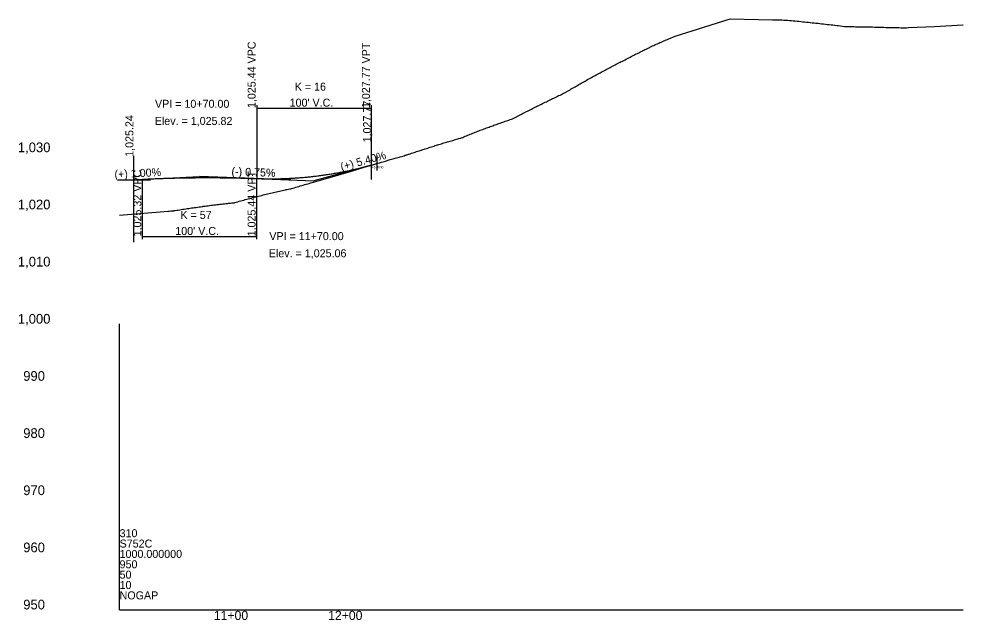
# Model space of a CAD drawing. Extents: x 1590191 to 1593577, y 1108634 to 1115609.
# Drawn here: x 1590191 to 1591017, y 1110634 to 1111160 of the extents above; entities that cross this region are included whole.
import ezdxf

# ---------------------------------------------------------------- set-up
doc = ezdxf.new("R2010")
doc.units = 0
for name, color, linetype in [('BR_USER NOTES', 7, 'Continuous'), ('RD_DDB_ElevTX', 7, 'Continuous'), ('RD_DDB_GradeTX', 7, 'Continuous'), ('RD_DDB_Profile_EX', 7, 'Continuous'), ('RD_DDB_Profile_Lbl', 7, 'Continuous'), ('RD_DDB_Profile_PR', 7, 'Continuous'), ('RD_DDB_StaTX', 7, 'Continuous'), ('RD_DDB_StripGrade', 7, 'Continuous'), ('RD_DDB_VCLbl', 7, 'Continuous'), ('RD_GPK_Profile_Cell', 7, 'Continuous')]:
    doc.layers.add(name, color=color, linetype=linetype)

msp = doc.modelspace()

# ---------------------------------------------------------------- linework, layer by layer
at = {"layer": 'BR_USER NOTES'}
for p, q in [((1590499.01, 1111048.43), (1590499.01, 1111019.91)), ((1590291.08, 1111040.52), (1590291.08, 1110965.03)), ((1590499.01, 1111032.31), (1590504.01, 1111033.78)), ((1590504.01, 1111040.83), (1590504.01, 1111027.61)), ((1590277.69, 1111019.67), (1590305.95, 1111019.67))]:
    msp.add_line(p, q, dxfattribs=at)
at = {"layer": 'RD_DDB_GradeTX'}
for p, q in [((1590499.01, 1111032.31), (1590449.01, 1111018.8)), ((1590291.08, 1111019.67), (1590349.01, 1111022.57)), ((1590428.95, 1111019.55), (1590349.01, 1111022.57)), ((1590369.07, 1111021.81), (1590449.01, 1111018.8))]:
    msp.add_line(p, q, dxfattribs=at)
at = {"layer": 'RD_DDB_Profile_EX'}
msp.add_lwpolyline([(1590279.01, 1110988.58), (1590289.38, 1110989.65), (1590314.38, 1110991.63), (1590321.21, 1110992.17), (1590322.52, 1110992.27), (1590323.82, 1110992.37), (1590325.12, 1110992.47), (1590326.42, 1110992.57), (1590326.86, 1110992.6), (1590327.76, 1110992.75), (1590329.02, 1110992.94), (1590330.33, 1110993.15), (1590331.63, 1110993.35), (1590332.93, 1110993.55), (1590334.23, 1110993.74), (1590335.53, 1110993.94), (1590336.84, 1110994.14), (1590338.14, 1110994.33), (1590339.44, 1110994.52), (1590340.74, 1110994.72), (1590342.04, 1110994.91), (1590343.34, 1110995.1), (1590344.65, 1110995.29), (1590345.95, 1110995.47), (1590347.25, 1110995.66), (1590348.55, 1110995.84), (1590349.85, 1110996.03), (1590351.16, 1110996.21), (1590351.84, 1110996.31), (1590352.46, 1110996.39), (1590353.01, 1110996.46), (1590353.76, 1110996.57), (1590355.06, 1110996.75), (1590356.36, 1110996.92), (1590357.67, 1110997.1), (1590358.97, 1110997.28), (1590360.27, 1110997.45), (1590361.57, 1110997.63), (1590362.39, 1110997.73), (1590362.87, 1110997.79), (1590364.17, 1110997.95), (1590365.48, 1110998.1), (1590366.78, 1110998.25), (1590368.08, 1110998.4), (1590369.38, 1110998.54), (1590370.68, 1110998.69), (1590371.99, 1110998.83), (1590373.29, 1110998.97), (1590374.22, 1110999.07), (1590374.59, 1110999.09), (1590375.89, 1110999.18), (1590377.19, 1110999.28), (1590378.49, 1110999.39), (1590379.26, 1110999.46), (1590379.8, 1110999.62), (1590381.1, 1111000), (1590382.4, 1111000.38), (1590383.7, 1111000.75), (1590385, 1111001.12), (1590386.31, 1111001.49), (1590387.61, 1111001.85), (1590388.91, 1111002.22), (1590390.21, 1111002.57), (1590391.51, 1111002.93), (1590392.81, 1111003.28), (1590394.12, 1111003.63), (1590395.42, 1111003.98), (1590396.72, 1111004.33), (1590398.02, 1111004.67), (1590398.38, 1111004.76), (1590399.32, 1111004.99), (1590400.63, 1111005.31), (1590401.93, 1111005.63), (1590403.23, 1111005.95), (1590403.99, 1111006.13), (1590404.62, 1111006.28), (1590405.83, 1111006.57), (1590407.13, 1111006.89), (1590408.44, 1111007.2), (1590409.74, 1111007.51), (1590411.04, 1111007.82), (1590412.34, 1111008.13), (1590413.64, 1111008.43), (1590414.95, 1111008.74), (1590416.25, 1111009.04), (1590417.55, 1111009.34), (1590418.85, 1111009.64), (1590420.15, 1111009.94), (1590421.45, 1111010.24), (1590422.76, 1111010.54), (1590424.06, 1111010.83), (1590424.64, 1111010.97), (1590425.36, 1111011.12), (1590426.66, 1111011.4), (1590427.96, 1111011.67), (1590428.48, 1111011.78), (1590429.27, 1111011.97), (1590430.57, 1111012.25), (1590431.87, 1111012.52), (1590433.17, 1111013), (1590434.47, 1111013.39), (1590435.77, 1111013.78), (1590437.08, 1111014.17), (1590438.38, 1111014.55), (1590439.68, 1111014.94), (1590440.98, 1111015.32), (1590442.28, 1111015.7), (1590443.59, 1111016.09), (1590444.89, 1111016.47), (1590446.19, 1111016.85), (1590447.49, 1111017.22), (1590447.49, 1111017.22), (1590456.83, 1111019.94), (1590481.79, 1111027.18), (1590481.83, 1111027.2), (1590492.91, 1111030.49), (1590494, 1111030.82), (1590495.1, 1111031.14), (1590496.19, 1111031.47), (1590497.28, 1111031.79), (1590498.37, 1111032.12), (1590499.46, 1111032.44), (1590500.56, 1111032.76), (1590501.65, 1111033.09), (1590502.74, 1111033.41), (1590503.83, 1111033.73), (1590504.92, 1111034.05), (1590506.02, 1111034.37), (1590506.65, 1111034.56), (1590507.11, 1111034.69), (1590508.2, 1111035.02), (1590509.29, 1111035.34), (1590510.38, 1111035.66), (1590511.56, 1111036.01), (1590512.57, 1111036.3), (1590513.66, 1111036.62), (1590514.75, 1111036.94), (1590515.84, 1111037.25), (1590516.94, 1111037.57), (1590518.03, 1111037.88), (1590519.12, 1111038.2), (1590520.21, 1111038.51), (1590521.3, 1111038.82), (1590522.4, 1111039.13), (1590523.49, 1111039.44), (1590524.58, 1111039.75), (1590525.67, 1111040.06), (1590526.76, 1111040.37), (1590527.86, 1111040.67), (1590528.95, 1111040.98), (1590529.64, 1111041.17), (1590530.04, 1111041.3), (1590531.13, 1111041.66), (1590531.75, 1111041.87), (1590532.23, 1111042.03), (1590533.32, 1111042.39), (1590534.41, 1111042.75), (1590535.5, 1111043.12), (1590536.59, 1111043.48), (1590537.69, 1111043.84), (1590538.78, 1111044.2), (1590539.87, 1111044.56), (1590540.96, 1111044.91), (1590542.05, 1111045.27), (1590543.15, 1111045.63), (1590544.24, 1111045.98), (1590545.33, 1111046.34), (1590546.42, 1111046.69), (1590547.51, 1111047.04), (1590548.61, 1111047.39), (1590549.7, 1111047.74), (1590550.79, 1111048.09), (1590551.88, 1111048.43), (1590552.97, 1111048.78), (1590554.07, 1111049.12), (1590554.56, 1111049.28), (1590555.16, 1111049.46), (1590556.25, 1111049.8), (1590557.03, 1111050.04), (1590557.34, 1111050.13), (1590558.43, 1111050.47), (1590559.53, 1111050.81), (1590560.62, 1111051.15), (1590561.71, 1111051.49), (1590562.8, 1111051.83), (1590563.9, 1111052.16), (1590564.99, 1111052.5), (1590565.97, 1111052.8), (1590567.17, 1111053.14), (1590568.26, 1111053.46), (1590569.36, 1111053.77), (1590570.45, 1111054.08), (1590571.54, 1111054.39), (1590572.63, 1111054.69), (1590573.72, 1111054.99), (1590574.84, 1111055.3), (1590575.91, 1111055.6), (1590577, 1111055.89), (1590577.63, 1111056.06), (1590578.09, 1111056.26), (1590579.18, 1111056.72), (1590580.28, 1111057.17), (1590581.37, 1111057.62), (1590582.46, 1111058.07), (1590583.55, 1111058.52), (1590584.64, 1111058.97), (1590585.74, 1111059.41), (1590586.83, 1111059.85), (1590587.92, 1111060.29), (1590589.01, 1111060.72), (1590590.1, 1111061.16), (1590591.2, 1111061.59), (1590592.29, 1111062.01), (1590593.38, 1111062.44), (1590594.47, 1111062.86), (1590595.57, 1111063.28), (1590596.66, 1111063.7), (1590597.83, 1111064.14), (1590598.84, 1111064.51), (1590599.93, 1111064.92), (1590601.03, 1111065.32), (1590602.24, 1111065.76), (1590603.21, 1111066.11), (1590604.3, 1111066.51), (1590605.39, 1111066.91), (1590606.49, 1111067.31), (1590607.24, 1111067.58), (1590607.58, 1111067.7), (1590608.67, 1111068.09), (1590609.76, 1111068.48), (1590610.85, 1111068.87), (1590611.95, 1111069.25), (1590613.04, 1111069.63), (1590614.13, 1111070.01), (1590615.22, 1111070.39), (1590616.31, 1111070.76), (1590617.41, 1111071.13), (1590618.5, 1111071.5), (1590619.59, 1111071.87), (1590620.68, 1111072.24), (1590621.77, 1111072.6), (1590622.87, 1111072.96), (1590623.96, 1111073.36), (1590625.05, 1111073.97), (1590626.14, 1111074.57), (1590626.47, 1111074.75), (1590627.23, 1111075.16), (1590628.33, 1111075.74), (1590629.42, 1111076.33), (1590630.51, 1111076.91), (1590631.6, 1111077.49), (1590632.7, 1111078.06), (1590633.4, 1111078.44), (1590633.79, 1111078.63), (1590634.88, 1111079.19), (1590635.97, 1111079.75), (1590637.06, 1111080.3), (1590638.16, 1111080.86), (1590639.25, 1111081.41), (1590640.34, 1111081.96), (1590641.43, 1111082.51), (1590642.52, 1111083.06), (1590643.62, 1111083.61), (1590644.71, 1111084.16), (1590645.8, 1111084.71), (1590646.89, 1111085.25), (1590647.3, 1111085.46), (1590647.98, 1111085.79), (1590649.08, 1111086.33), (1590649.48, 1111086.53), (1590650.17, 1111086.84), (1590650.76, 1111087.12), (1590651.26, 1111087.36), (1590652.35, 1111087.9), (1590653.44, 1111088.44), (1590654.54, 1111088.98), (1590655.63, 1111089.51), (1590656.72, 1111090.05), (1590657.81, 1111090.58), (1590658.9, 1111091.12), (1590660, 1111091.65), (1590661.09, 1111092.18), (1590662.18, 1111092.71), (1590663.27, 1111093.23), (1590664.37, 1111093.76), (1590665.46, 1111094.29), (1590666.55, 1111094.81), (1590667.64, 1111095.33), (1590668.76, 1111095.87), (1590669.83, 1111096.47), (1590670.31, 1111096.74), (1590670.92, 1111097.1), (1590672.01, 1111097.74), (1590673.1, 1111098.39), (1590674.19, 1111099.03), (1590675.29, 1111099.67), (1590676.38, 1111100.3), (1590677.47, 1111100.94), (1590678.56, 1111101.57), (1590679.65, 1111102.2), (1590680.75, 1111102.84), (1590681.84, 1111103.46), (1590682.93, 1111104.09), (1590684.02, 1111104.72), (1590685.11, 1111105.34), (1590686.21, 1111105.96), (1590687.3, 1111106.58), (1590688.39, 1111107.2), (1590689.48, 1111107.81), (1590690.57, 1111108.43), (1590691.87, 1111109.15), (1590692.76, 1111109.64), (1590693.85, 1111110.23), (1590694.94, 1111110.82), (1590696.03, 1111111.41), (1590697.13, 1111112), (1590698.22, 1111112.59), (1590699.31, 1111113.17), (1590700.4, 1111113.77), (1590701.5, 1111114.36), (1590702.59, 1111114.95), (1590703.68, 1111115.54), (1590704.77, 1111116.12), (1590705.86, 1111116.7), (1590706.96, 1111117.29), (1590708.05, 1111117.86), (1590709.14, 1111118.44), (1590710.23, 1111119.01), (1590711.32, 1111119.58), (1590712.42, 1111120.15), (1590713.51, 1111120.72), (1590714.6, 1111121.28), (1590715.08, 1111121.53), (1590715.69, 1111121.84), (1590716.78, 1111122.38), (1590717.92, 1111122.93), (1590718.97, 1111123.48), (1590720.06, 1111124.06), (1590721.15, 1111124.63), (1590722.24, 1111125.2), (1590723.34, 1111125.76), (1590724.43, 1111126.33), (1590725.52, 1111126.89), (1590726.61, 1111127.45), (1590727.7, 1111128), (1590728.8, 1111128.56), (1590729.89, 1111129.11), (1590730.98, 1111129.66), (1590732.07, 1111130.2), (1590733.17, 1111130.74), (1590734.26, 1111131.28), (1590735.35, 1111131.82), (1590736.07, 1111132.17), (1590736.44, 1111132.36), (1590737.53, 1111132.91), (1590738.63, 1111133.46), (1590739.72, 1111134), (1590740.81, 1111134.54), (1590741.9, 1111135.07), (1590742.99, 1111135.6), (1590744.09, 1111136.13), (1590745.18, 1111136.64), (1590746.27, 1111137.14), (1590747.36, 1111137.64), (1590748.45, 1111138.14), (1590749.55, 1111138.63), (1590750.64, 1111139.12), (1590751.73, 1111139.61), (1590752.82, 1111140.09), (1590753.91, 1111140.57), (1590755.01, 1111141.05), (1590756.1, 1111141.52), (1590757.19, 1111141.99), (1590758.28, 1111142.45), (1590759.37, 1111142.91), (1590765.13, 1111145.32), (1590790.07, 1111153.14), (1590813.06, 1111160.35), (1590838.05, 1111159.85), (1590850.2, 1111159.6), (1590851.85, 1111159.56), (1590853.54, 1111159.53), (1590855.16, 1111159.49), (1590856.81, 1111159.45), (1590858.46, 1111159.4), (1590860.11, 1111159.36), (1590861.76, 1111159.31), (1590863.04, 1111159.25), (1590863.41, 1111159.22), (1590865.06, 1111159.08), (1590866.11, 1111158.99), (1590866.71, 1111158.92), (1590868.36, 1111158.75), (1590870.01, 1111158.58), (1590871.66, 1111158.41), (1590873.31, 1111158.24), (1590874.96, 1111158.07), (1590876.61, 1111157.89), (1590878.26, 1111157.72), (1590879.91, 1111157.54), (1590881.57, 1111157.36), (1590883.22, 1111157.18), (1590884.87, 1111157), (1590886.52, 1111156.82), (1590888.17, 1111156.65), (1590890.1, 1111156.48), (1590891.47, 1111156.33), (1590893.12, 1111156.14), (1590894.77, 1111155.96), (1590896.42, 1111155.77), (1590898.07, 1111155.58), (1590899.72, 1111155.39), (1590901.37, 1111155.2), (1590903.02, 1111155.01), (1590904.67, 1111154.82), (1590906.32, 1111154.62), (1590907.98, 1111154.43), (1590909.63, 1111154.23), (1590911.28, 1111154.03), (1590913.08, 1111153.82), (1590914.58, 1111153.64), (1590914.89, 1111153.63), (1590916.23, 1111153.62), (1590917.88, 1111153.59), (1590919.53, 1111153.57), (1590921.18, 1111153.55), (1590922.83, 1111153.52), (1590924.48, 1111153.5), (1590926.13, 1111153.47), (1590927.78, 1111153.44), (1590929.43, 1111153.42), (1590931.08, 1111153.39), (1590932.73, 1111153.36), (1590934.39, 1111153.33), (1590936.04, 1111153.29), (1590937.69, 1111153.26), (1590939.36, 1111153.23), (1590940.99, 1111153.15), (1590941.8, 1111153.11), (1590942.64, 1111153.1), (1590944.29, 1111153.06), (1590945.94, 1111153.03), (1590947.59, 1111152.99), (1590949.24, 1111152.95), (1590950.89, 1111152.92), (1590952.54, 1111152.88), (1590954.19, 1111152.85), (1590955.84, 1111152.81), (1590957.49, 1111152.77), (1590959.14, 1111152.73), (1590960.79, 1111152.69), (1590962.45, 1111152.65), (1590964.1, 1111152.62), (1590964.56, 1111152.6), (1590965.75, 1111152.58), (1590966.66, 1111152.55), (1590967.4, 1111152.58), (1590969.05, 1111152.67), (1590991.77, 1111153.79), (1591016.77, 1111155.03), (1591016.92, 1111155.04)], dxfattribs=at)
at = {"layer": 'RD_DDB_Profile_PR'}
msp.add_line((1590291.08, 1111019.67), (1590299.01, 1111020.07), dxfattribs=at)
for points in [[(1590399.01, 1111020.68), (1590401.01, 1111020.61), (1590403.01, 1111020.56), (1590405.01, 1111020.51), (1590407.01, 1111020.48), (1590409.01, 1111020.46), (1590411.01, 1111020.45), (1590413.01, 1111020.46), (1590415.01, 1111020.47), (1590417.01, 1111020.5), (1590419.01, 1111020.54), (1590421.01, 1111020.6), (1590423.01, 1111020.66), (1590425.01, 1111020.74), (1590427.01, 1111020.83), (1590429.01, 1111020.94), (1590431.01, 1111021.05), (1590433.01, 1111021.18), (1590435.01, 1111021.32), (1590437.01, 1111021.47), (1590439.01, 1111021.64), (1590441.01, 1111021.81), (1590443.01, 1111022), (1590445.01, 1111022.21), (1590447.01, 1111022.42), (1590449.01, 1111022.65), (1590451.01, 1111022.88), (1590453.01, 1111023.14), (1590455.01, 1111023.4), (1590457.01, 1111023.67), (1590459.01, 1111023.96), (1590461.01, 1111024.26), (1590463.01, 1111024.57), (1590465.01, 1111024.9), (1590467.01, 1111025.24), (1590469.01, 1111025.59), (1590471.01, 1111025.95), (1590473.01, 1111026.32), (1590475.01, 1111026.71), (1590477.01, 1111027.11), (1590479.01, 1111027.52), (1590481.01, 1111027.94), (1590483.01, 1111028.38), (1590485.01, 1111028.83), (1590487.01, 1111029.29), (1590489.01, 1111029.76), (1590491.01, 1111030.24), (1590493.01, 1111030.74), (1590495.01, 1111031.25), (1590497.01, 1111031.77), (1590499.01, 1111032.31)], [(1590299.01, 1111020.07), (1590301.01, 1111020.17), (1590303.01, 1111020.26), (1590305.01, 1111020.36), (1590307.01, 1111020.44), (1590309.01, 1111020.53), (1590311.01, 1111020.61), (1590313.01, 1111020.69), (1590315.01, 1111020.76), (1590317.01, 1111020.83), (1590319.01, 1111020.9), (1590321.01, 1111020.96), (1590323.01, 1111021.02), (1590325.01, 1111021.07), (1590327.01, 1111021.13), (1590329.01, 1111021.18), (1590331.01, 1111021.22), (1590333.01, 1111021.26), (1590335.01, 1111021.3), (1590337.01, 1111021.34), (1590339.01, 1111021.37), (1590341.01, 1111021.4), (1590343.01, 1111021.42), (1590345.01, 1111021.44), (1590347.01, 1111021.46), (1590349.01, 1111021.47), (1590351.01, 1111021.48), (1590353.01, 1111021.49), (1590355.01, 1111021.5), (1590357.01, 1111021.5), (1590359.01, 1111021.49), (1590361.01, 1111021.48), (1590363.01, 1111021.47), (1590365.01, 1111021.46), (1590367.01, 1111021.44), (1590369.01, 1111021.42), (1590371.01, 1111021.4), (1590373.01, 1111021.37), (1590375.01, 1111021.34), (1590377.01, 1111021.3), (1590379.01, 1111021.26), (1590381.01, 1111021.22), (1590383.01, 1111021.18), (1590385.01, 1111021.13), (1590387.01, 1111021.07), (1590389.01, 1111021.02), (1590391.01, 1111020.96), (1590393.01, 1111020.89), (1590395.01, 1111020.83), (1590397.01, 1111020.76), (1590399.01, 1111020.68)]]:
    msp.add_spline(points, degree=3, dxfattribs=at)
at = {"layer": 'RD_DDB_VCLbl'}
for p, q in [((1590399.01, 1111084.81), (1590399.01, 1111020.68)), ((1590499.01, 1111084.81), (1590499.01, 1111032.31)), ((1590399.01, 1111082.31), (1590499.01, 1111082.31)), ((1590299.01, 1110967.57), (1590299.01, 1111020.07)), ((1590399.01, 1110967.57), (1590399.01, 1111020.68)), ((1590299.01, 1110970.07), (1590399.01, 1110970.07))]:
    msp.add_line(p, q, dxfattribs=at)
at = {"layer": 'RD_GPK_Profile_Cell'}
for q in [(1590279.01, 1110893.47), (1591016.92, 1110643.47), (1590279.01, 1110643.47)]:
    msp.add_line((1590279.01, 1110643.47), q, dxfattribs=at)

# ---------------------------------------------------------------- texts
at = {"layer": 'BR_USER NOTES'}
msp.add_text('+5.9040', height=2, dxfattribs=at).set_placement((1590499.7, 1111029.61))
at = {"layer": 'RD_DDB_ElevTX'}
for s, p in [('1,030', (1590190.05, 1111043.72)), ('1,020', (1590190.05, 1110993.72)), ('1,010', (1590190.05, 1110943.72)), ('1,000', (1590190.05, 1110893.72)), ('990', (1590194.73, 1110843.72)), ('980', (1590194.73, 1110793.72)), ('970', (1590194.73, 1110743.72)), ('960', (1590194.73, 1110693.72)), ('950', (1590194.73, 1110643.72))]:
    msp.add_text(s, height=8.5, dxfattribs=at).set_placement(p)
at = {"layer": 'RD_DDB_GradeTX'}
for s, rotation, p in [('(+) 5.40%', 15.12026, (1590473.27, 1111027.42)), ('(+) 1.00%', 2.86241, (1590274.68, 1111020.86)), ('(-) 0.75%', 357.83819, (1590376.75, 1111023.53)), ('(-) 0.75%', 357.83819, (1590376.82, 1111023.52))]:
    msp.add_text(s, height=7, rotation=rotation, dxfattribs=at).set_placement(p)
at = {"layer": 'RD_DDB_Profile_Lbl'}
for s, p in [('VPI = 10+70.00', (1590309.99, 1111082.57)), ('Elev. = 1,025.82', (1590309.79, 1111067.57)), ('VPI = 11+70.00', (1590409.99, 1110966.8)), ('Elev. = 1,025.06', (1590409.55, 1110951.8))]:
    msp.add_text(s, height=7, dxfattribs=at).set_placement(p)
for s, p in [('1,027.77', (1590499.01, 1111052.31)), ('1,025.24', (1590291.08, 1111039.67))]:
    msp.add_text(s, height=7, rotation=90, dxfattribs=at).set_placement(p)
at = {"layer": 'RD_DDB_StaTX'}
for s, p in [('11+00', (1590361.42, 1110634.47)), ('12+00', (1590461.42, 1110634.47))]:
    msp.add_text(s, height=8, dxfattribs=at).set_placement(p)
at = {"layer": 'RD_DDB_StripGrade'}
for s, p in [('1,025.44 VPC', (1590398.01, 1111082.31)), ('1,027.77 VPT', (1590498.01, 1111082.31)), ('1,025.32 VPC', (1590298.01, 1110970.07)), ('1,025.44 VPT', (1590398.01, 1110970.07))]:
    msp.add_text(s, height=7, rotation=90, dxfattribs=at).set_placement(p)
at = {"layer": 'RD_DDB_VCLbl'}
for s, p in [('K = 16', (1590432.23, 1111097.56)), ("100' V.C.", (1590427.76, 1111083.56)), ('K = 57', (1590332.23, 1110985.32)), ("100' V.C.", (1590327.76, 1110971.32))]:
    msp.add_text(s, height=7, dxfattribs=at).set_placement(p)
at = {"layer": 'RD_GPK_Profile_Cell'}
for s, p in [('310', (1590279.01, 1110706.89)), ('S752C', (1590279.01, 1110697.83)), ('1000.000000', (1590279.01, 1110688.77)), ('950', (1590279.01, 1110679.71)), ('50', (1590279.01, 1110670.65)), ('10', (1590279.01, 1110661.59)), ('NOGAP', (1590279.01, 1110652.53))]:
    msp.add_text(s, height=7, dxfattribs=at).set_placement(p)

doc.saveas('drawing.dxf')
